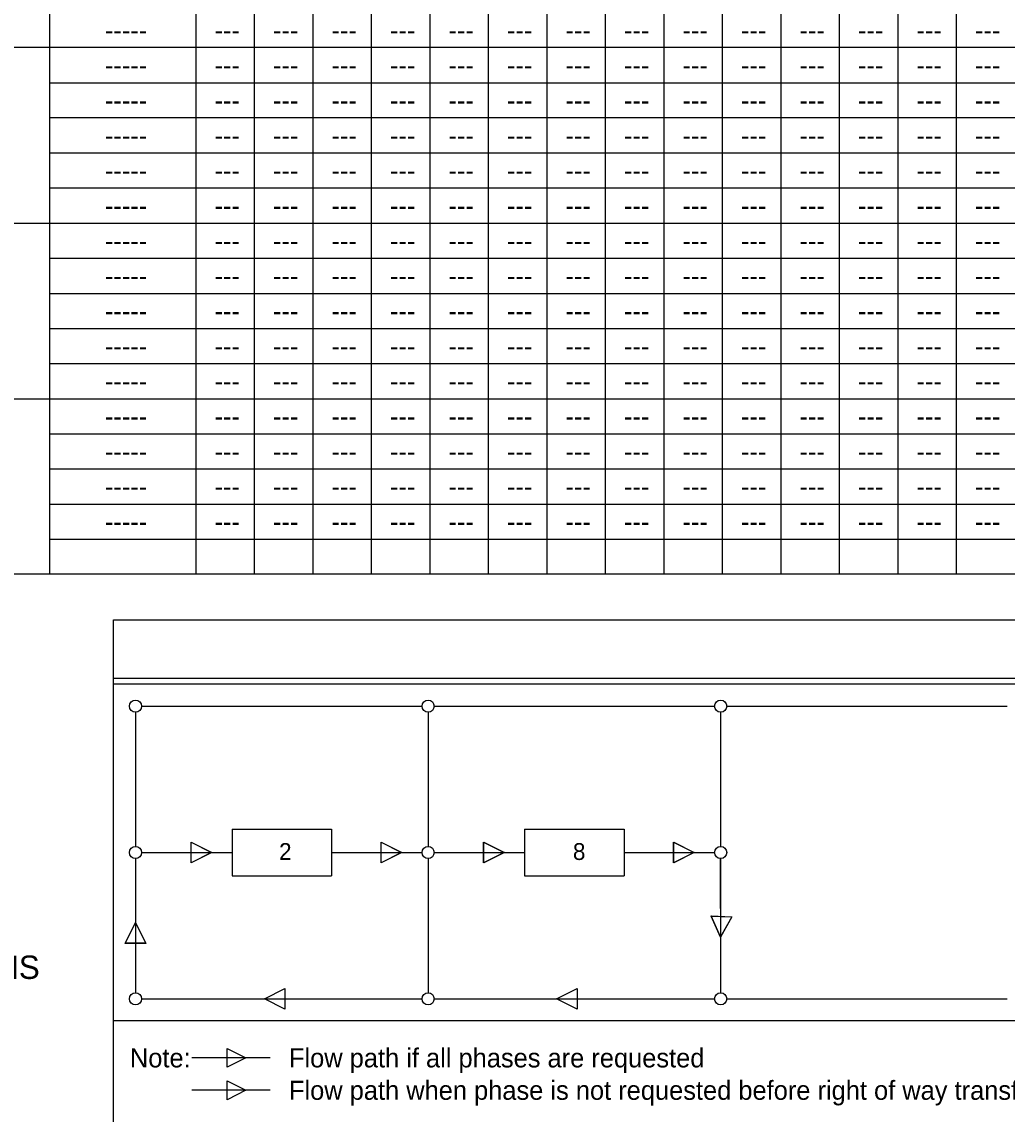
# Model space of a CAD drawing. Extents: x 10040 to 81668, y 7194 to 11018.
# Drawn here: x 10806 to 11479, y 8516 to 9263 of the extents above; entities that cross this region are included whole.
import ezdxf

# ---------------------------------------------------------------- set-up
doc = ezdxf.new("R2010")
doc.units = 0
for name, color, linetype in [('dsnStdTable', 7, 'Continuous'), ('Level 4', 7, 'Continuous'), ('wetSpecialNote', 7, 'Continuous')]:
    doc.layers.add(name, color=color, linetype=linetype)

msp = doc.modelspace()

# ---------------------------------------------------------------- linework, layer by layer
at = {"layer": 'Level 4'}
for p, q in [((10924.49, 9889.02), (10924.49, 8884.96)), ((10924.49, 9889.02), (10924.49, 8884.97)), ((11124.49, 9889.02), (11124.49, 8884.97)), ((11124.49, 9889.02), (11124.49, 8884.97)), ((11324.49, 9889.02), (11324.49, 8884.97)), ((11324.49, 9889.02), (11324.49, 8884.97)), ((10824.49, 9689.01), (10824.49, 8884.96)), ((10964.49, 9665.02), (10964.49, 8884.97)), ((11164.49, 9665.02), (11164.49, 8884.97)), ((11364.49, 9665.02), (11364.49, 8884.97)), ((11004.49, 9641.02), (11004.49, 8884.97)), ((11044.49, 9641.02), (11044.49, 8884.97)), ((11084.49, 9641.02), (11084.49, 8884.97)), ((11204.49, 9641.02), (11204.49, 8884.97)), ((11244.49, 9641.02), (11244.49, 8884.97)), ((11284.49, 9641.02), (11284.49, 8884.97)), ((11404.49, 9641.02), (11404.49, 8884.97)), ((11444.49, 9641.02), (11444.49, 8884.97)), ((12518.28, 8809.82), (10868.28, 8809.82)), ((10883.28, 8790.69), (10883.28, 8698.92)), ((10887.41, 8794.82), (11079.21, 8794.82)), ((11083.33, 8790.69), (11083.33, 8698.92)), ((11087.46, 8794.82), (11279.26, 8794.82)), ((11283.39, 8790.69), (11283.39, 8698.92)), ((11287.52, 8794.82), (11479.31, 8794.82)), ((10949.3, 8710.8), (11017.32, 8710.8)), ((10949.3, 8710.8), (10949.3, 8678.79)), ((11017.32, 8710.8), (11017.32, 8678.79)), ((11149.35, 8710.8), (11217.37, 8710.8)), ((11149.35, 8710.8), (11149.35, 8678.79)), ((11217.37, 8710.8), (11217.37, 8678.79)), ((10921.23, 8687.79), (10921.23, 8701.8)), ((10921.23, 8701.8), (10935.24, 8694.79)), ((10921.42, 8687.79), (10921.42, 8701.8)), ((10921.42, 8701.8), (10935.42, 8694.79)), ((11051.14, 8687.79), (11051.14, 8701.8)), ((11051.14, 8701.8), (11065.14, 8694.79)), ((11051.32, 8687.79), (11051.32, 8701.8)), ((11051.32, 8701.8), (11065.33, 8694.79)), ((11121.29, 8687.79), (11121.29, 8701.8)), ((11121.29, 8701.8), (11135.29, 8694.79)), ((11121.47, 8687.79), (11121.47, 8701.8)), ((11121.47, 8701.8), (11135.48, 8694.79)), ((11251.19, 8687.79), (11251.19, 8701.8)), ((11251.19, 8701.8), (11265.2, 8694.79)), ((11251.38, 8687.79), (11251.38, 8701.8)), ((11251.38, 8701.8), (11265.38, 8694.79)), ((10887.41, 8694.79), (10949.3, 8694.79)), ((10935.24, 8694.79), (10921.23, 8687.79)), ((10935.42, 8694.79), (10921.42, 8687.79)), ((11017.32, 8694.79), (11079.21, 8694.79)), ((11065.14, 8694.79), (11051.14, 8687.79)), ((11065.33, 8694.79), (11051.32, 8687.79)), ((11087.46, 8694.79), (11149.35, 8694.79)), ((11135.29, 8694.79), (11121.29, 8687.79)), ((11135.48, 8694.79), (11121.47, 8687.79)), ((11217.37, 8694.79), (11279.26, 8694.79)), ((11265.2, 8694.79), (11251.19, 8687.79)), ((11265.38, 8694.79), (11251.38, 8687.79)), ((10883.28, 8690.66), (10883.28, 8598.9)), ((11083.33, 8690.66), (11083.33, 8598.9)), ((11283.39, 8656.66), (11283.39, 8690.66)), ((11283.39, 8690.66), (11283.39, 8598.9)), ((10949.3, 8678.79), (11017.32, 8678.79)), ((11149.35, 8678.79), (11217.37, 8678.79)), ((10876.28, 8632.91), (10883.28, 8646.91)), ((10876.28, 8632.72), (10883.28, 8646.73)), ((10876.28, 8632.72), (10883.28, 8646.73)), ((10883.28, 8646.91), (10890.28, 8632.91)), ((10883.28, 8646.73), (10890.28, 8632.72)), ((10883.28, 8646.73), (10890.28, 8632.72)), ((11276.96, 8651.5), (11290.96, 8650.93)), ((11283.4, 8637.22), (11276.96, 8651.5)), ((11276.96, 8651.32), (11290.95, 8650.75)), ((11283.39, 8637.04), (11276.96, 8651.32)), ((11290.95, 8650.75), (11283.39, 8637.04)), ((11290.96, 8650.93), (11283.4, 8637.22)), ((10890.28, 8632.91), (10876.28, 8632.91)), ((10890.28, 8632.72), (10876.28, 8632.72)), ((10890.28, 8632.72), (10876.28, 8632.72)), ((10971.36, 8594.77), (10985.36, 8601.77)), ((10985.36, 8601.77), (10985.36, 8587.77)), ((11171.23, 8594.77), (11185.23, 8601.77)), ((11185.23, 8601.77), (11185.23, 8587.77)), ((10887.41, 8594.77), (11079.21, 8594.77)), ((10985.36, 8587.77), (10971.36, 8594.77)), ((11087.46, 8594.77), (11279.26, 8594.77)), ((11185.23, 8587.77), (11171.23, 8594.77)), ((11287.52, 8594.77), (11479.31, 8594.77)), ((12518.28, 8579.77), (10868.28, 8579.77)), ((10945.86, 8548.03), (10945.86, 8560.95)), ((10945.86, 8560.95), (10958.78, 8554.49)), ((10945.86, 8548.03), (10945.86, 8560.95)), ((10945.86, 8560.95), (10958.78, 8554.49)), ((10975.32, 8554.49), (10921.8, 8554.49)), ((10958.78, 8554.49), (10945.86, 8548.03)), ((10958.78, 8554.49), (10945.86, 8548.03)), ((10945.87, 8525.88), (10945.87, 8538.8)), ((10945.87, 8538.8), (10958.78, 8532.34)), ((10975.32, 8532.34), (10921.8, 8532.34)), ((10958.78, 8532.34), (10945.87, 8525.88))]:
    msp.add_line(p, q, dxfattribs=at)
for points in [[(10664.49, 9929.02), (12524.49, 9929.02), (12524.49, 8884.97), (10664.49, 8884.97)], [(10868.28, 8853.82), (12518.28, 8853.82), (12518.28, 8503.82), (10868.28, 8503.82)]]:
    msp.add_lwpolyline(points, close=True, dxfattribs=at)
msp.add_lwpolyline([(12518.28, 8813.82), (10868.28, 8813.82)], dxfattribs=at)
for centre in [(10883.28, 8794.82), (11083.33, 8794.82), (11283.39, 8794.82), (10883.28, 8694.79), (11083.33, 8694.79), (11283.39, 8694.79), (10883.28, 8594.77), (11083.33, 8594.77), (11283.39, 8594.77)]:
    msp.add_circle(centre, 4.13, dxfattribs=at)
at = {"layer": 'wetSpecialNote'}
for p, q in [((12524.49, 9244.98), (10664.49, 9244.98)), ((10824.49, 9220.98), (12524.49, 9220.98)), ((12524.49, 9196.98), (10824.49, 9196.98)), ((10824.49, 9172.98), (12524.49, 9172.98)), ((12524.49, 9148.98), (10824.49, 9148.98)), ((10664.49, 9124.98), (12524.49, 9124.98)), ((10824.49, 9100.97), (12524.49, 9100.97)), ((10824.49, 9076.97), (12524.49, 9076.97)), ((10824.49, 9052.97), (12524.49, 9052.97)), ((10824.49, 9028.97), (12524.49, 9028.97)), ((10664.49, 9004.97), (12524.49, 9004.97)), ((10824.49, 8980.97), (12524.49, 8980.97)), ((10824.49, 8956.97), (12524.49, 8956.97)), ((10824.49, 8932.97), (12524.49, 8932.97)), ((10824.49, 8908.96), (12524.49, 8908.96))]:
    msp.add_line(p, q, dxfattribs=at)

# ---------------------------------------------------------------- texts
at = {"layer": 'dsnStdTable'}
for s, p in [('-----', (10862.33, 9250.48)), ('---', (10937.28, 9250.48)), ('---', (10977.28, 9250.48)), ('---', (11017.28, 9250.48)), ('---', (11057.28, 9250.48)), ('---', (11097.28, 9250.48)), ('---', (11137.28, 9250.48)), ('---', (11177.28, 9250.48)), ('---', (11217.28, 9250.48)), ('---', (11257.28, 9250.48)), ('---', (11297.28, 9250.48)), ('---', (11337.28, 9250.48)), ('---', (11377.28, 9250.48)), ('---', (11417.28, 9250.48)), ('---', (11457.28, 9250.48)), ('-----', (10862.33, 9226.48)), ('---', (10937.28, 9226.48)), ('---', (10977.28, 9226.48)), ('---', (11017.28, 9226.48)), ('---', (11057.28, 9226.48)), ('---', (11097.28, 9226.48)), ('---', (11137.28, 9226.48)), ('---', (11177.28, 9226.48)), ('---', (11217.28, 9226.48)), ('---', (11257.28, 9226.48)), ('---', (11297.28, 9226.48)), ('---', (11337.28, 9226.48)), ('---', (11377.28, 9226.48)), ('---', (11417.28, 9226.48)), ('---', (11457.28, 9226.48)), ('-----', (10862.33, 9202.48)), ('---', (10937.28, 9202.48)), ('---', (10977.28, 9202.48)), ('---', (11017.28, 9202.48)), ('---', (11057.28, 9202.48)), ('---', (11097.28, 9202.48)), ('---', (11137.28, 9202.48)), ('---', (11177.28, 9202.48)), ('---', (11217.28, 9202.48)), ('---', (11257.28, 9202.48)), ('---', (11297.28, 9202.48)), ('---', (11337.28, 9202.48)), ('---', (11377.28, 9202.48)), ('---', (11417.28, 9202.48)), ('---', (11457.28, 9202.48)), ('-----', (10862.33, 9178.48)), ('---', (10937.28, 9178.48)), ('---', (10977.28, 9178.48)), ('---', (11017.28, 9178.48)), ('---', (11057.28, 9178.48)), ('---', (11097.28, 9178.48)), ('---', (11137.28, 9178.48)), ('---', (11177.28, 9178.48)), ('---', (11217.28, 9178.48)), ('---', (11257.28, 9178.48)), ('---', (11297.28, 9178.48)), ('---', (11337.28, 9178.48)), ('---', (11377.28, 9178.48)), ('---', (11417.28, 9178.48)), ('---', (11457.28, 9178.48)), ('-----', (10862.33, 9154.48)), ('---', (10937.28, 9154.48)), ('---', (10977.28, 9154.48)), ('---', (11017.28, 9154.48)), ('---', (11057.28, 9154.48)), ('---', (11097.28, 9154.48)), ('---', (11137.28, 9154.48)), ('---', (11177.28, 9154.48)), ('---', (11217.28, 9154.48)), ('---', (11257.28, 9154.48)), ('---', (11297.28, 9154.48)), ('---', (11337.28, 9154.48)), ('---', (11377.28, 9154.48)), ('---', (11417.28, 9154.48)), ('---', (11457.28, 9154.48)), ('-----', (10862.33, 9130.48)), ('---', (10937.28, 9130.48)), ('---', (10977.28, 9130.48)), ('---', (11017.28, 9130.48)), ('---', (11057.28, 9130.48)), ('---', (11097.28, 9130.48)), ('---', (11137.28, 9130.48)), ('---', (11177.28, 9130.48)), ('---', (11217.28, 9130.48)), ('---', (11257.28, 9130.48)), ('---', (11297.28, 9130.48)), ('---', (11337.28, 9130.48)), ('---', (11377.28, 9130.48)), ('---', (11417.28, 9130.48)), ('---', (11457.28, 9130.48)), ('-----', (10862.33, 9106.48)), ('---', (10937.28, 9106.48)), ('---', (10977.28, 9106.48)), ('---', (11017.28, 9106.48)), ('---', (11057.28, 9106.48)), ('---', (11097.28, 9106.48)), ('---', (11137.28, 9106.48)), ('---', (11177.28, 9106.48)), ('---', (11217.28, 9106.48)), ('---', (11257.28, 9106.48)), ('---', (11297.28, 9106.48)), ('---', (11337.28, 9106.48)), ('---', (11377.28, 9106.48)), ('---', (11417.28, 9106.48)), ('---', (11457.28, 9106.48)), ('-----', (10862.33, 9082.47)), ('---', (10937.28, 9082.47)), ('---', (10977.28, 9082.47)), ('---', (11017.28, 9082.47)), ('---', (11057.28, 9082.47)), ('---', (11097.28, 9082.47)), ('---', (11137.28, 9082.47)), ('---', (11177.28, 9082.47)), ('---', (11217.28, 9082.47)), ('---', (11257.28, 9082.47)), ('---', (11297.28, 9082.47)), ('---', (11337.28, 9082.47)), ('---', (11377.28, 9082.47)), ('---', (11417.28, 9082.47)), ('---', (11457.28, 9082.47)), ('-----', (10862.33, 9058.47)), ('---', (10937.28, 9058.47)), ('---', (10977.28, 9058.47)), ('---', (11017.28, 9058.47)), ('---', (11057.28, 9058.47)), ('---', (11097.28, 9058.47)), ('---', (11137.28, 9058.47)), ('---', (11177.28, 9058.47)), ('---', (11217.28, 9058.47)), ('---', (11257.28, 9058.47)), ('---', (11297.28, 9058.47)), ('---', (11337.28, 9058.47)), ('---', (11377.28, 9058.47)), ('---', (11417.28, 9058.47)), ('---', (11457.28, 9058.47)), ('-----', (10862.33, 9034.47)), ('---', (10937.28, 9034.47)), ('---', (10977.28, 9034.47)), ('---', (11017.28, 9034.47)), ('---', (11057.28, 9034.47)), ('---', (11097.28, 9034.47)), ('---', (11137.28, 9034.47)), ('---', (11177.28, 9034.47)), ('---', (11217.28, 9034.47)), ('---', (11257.28, 9034.47)), ('---', (11297.28, 9034.47)), ('---', (11337.28, 9034.47)), ('---', (11377.28, 9034.47)), ('---', (11417.28, 9034.47)), ('---', (11457.28, 9034.47)), ('-----', (10862.33, 9010.47)), ('---', (10937.28, 9010.47)), ('---', (10977.28, 9010.47)), ('---', (11017.28, 9010.47)), ('---', (11057.28, 9010.47)), ('---', (11097.28, 9010.47)), ('---', (11137.28, 9010.47)), ('---', (11177.28, 9010.47)), ('---', (11217.28, 9010.47)), ('---', (11257.28, 9010.47)), ('---', (11297.28, 9010.47)), ('---', (11337.28, 9010.47)), ('---', (11377.28, 9010.47)), ('---', (11417.28, 9010.47)), ('---', (11457.28, 9010.47)), ('-----', (10862.33, 8986.47)), ('---', (10937.28, 8986.47)), ('---', (10977.28, 8986.47)), ('---', (11017.28, 8986.47)), ('---', (11057.28, 8986.47)), ('---', (11097.28, 8986.47)), ('---', (11137.28, 8986.47)), ('---', (11177.28, 8986.47)), ('---', (11217.28, 8986.47)), ('---', (11257.28, 8986.47)), ('---', (11297.28, 8986.47)), ('---', (11337.28, 8986.47)), ('---', (11377.28, 8986.47)), ('---', (11417.28, 8986.47)), ('---', (11457.28, 8986.47)), ('-----', (10862.33, 8962.47)), ('---', (10937.28, 8962.47)), ('---', (10977.28, 8962.47)), ('---', (11017.28, 8962.47)), ('---', (11057.28, 8962.47)), ('---', (11097.28, 8962.47)), ('---', (11137.28, 8962.47)), ('---', (11177.28, 8962.47)), ('---', (11217.28, 8962.47)), ('---', (11257.28, 8962.47)), ('---', (11297.28, 8962.47)), ('---', (11337.28, 8962.47)), ('---', (11377.28, 8962.47)), ('---', (11417.28, 8962.47)), ('---', (11457.28, 8962.47)), ('-----', (10862.33, 8938.47)), ('---', (10937.28, 8938.47)), ('---', (10977.28, 8938.47)), ('---', (11017.28, 8938.47)), ('---', (11057.28, 8938.47)), ('---', (11097.28, 8938.47)), ('---', (11137.28, 8938.47)), ('---', (11177.28, 8938.47)), ('---', (11217.28, 8938.47)), ('---', (11257.28, 8938.47)), ('---', (11297.28, 8938.47)), ('---', (11337.28, 8938.47)), ('---', (11377.28, 8938.47)), ('---', (11417.28, 8938.47)), ('---', (11457.28, 8938.47)), ('-----', (10862.33, 8914.46)), ('---', (10937.28, 8914.46)), ('---', (10977.28, 8914.46)), ('---', (11017.28, 8914.46)), ('---', (11057.28, 8914.46)), ('---', (11097.28, 8914.46)), ('---', (11137.28, 8914.46)), ('---', (11177.28, 8914.46)), ('---', (11217.28, 8914.46)), ('---', (11257.28, 8914.46)), ('---', (11297.28, 8914.46)), ('---', (11337.28, 8914.46)), ('---', (11377.28, 8914.46)), ('---', (11417.28, 8914.46)), ('---', (11457.28, 8914.46))]:
    msp.add_text(s, height=13, dxfattribs=at).set_placement(p)
at = {"layer": 'Level 4'}
for s, height, p in [('2', 11.52, (10981.42, 8689.73)), ('8', 11.52, (11182.37, 8689.73)), ('FLASHING OPERATIONS', 16, (10564.54, 8608.41)), ('Note:', 13, (10879.43, 8547.93)), ('Flow path if all phases are requested', 13, (10988.19, 8547.93)), ('Flow path when phase is not requested before right of way transfer', 13, (10988.19, 8525.79))]:
    msp.add_text(s, height=height, dxfattribs=at).set_placement(p)

doc.saveas('drawing.dxf')
